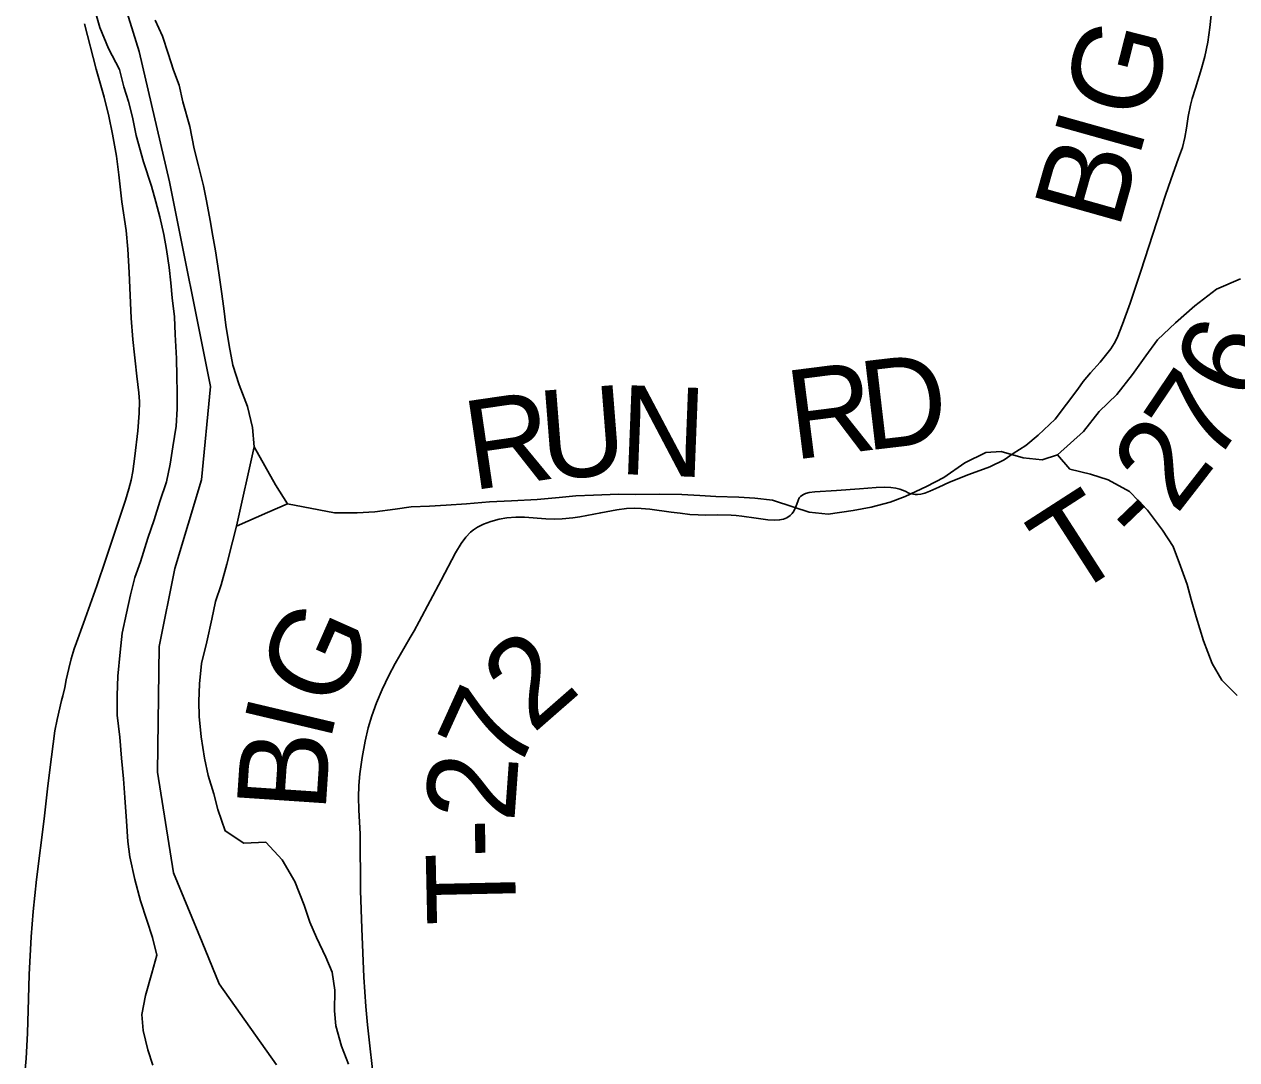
# Model space of a CAD drawing. Extents: x 1451455 to 1749751, y 218250 to 574981.
# Drawn here: x 1553110 to 1557194, y 292724 to 296211 of the extents above; entities that cross this region are included whole.
import ezdxf

# ---------------------------------------------------------------- set-up
doc = ezdxf.new("R2010")
doc.units = 0
for name, color, linetype in [('GM_X_Major_River', 7, 'Continuous'), ('GM_X_Minor_River', 7, 'Continuous'), ('GM_X_State_Route', 7, 'Continuous'), ('GM_X_Township', 7, 'Continuous'), ('GM_X_Township_Road', 7, 'Continuous'), ('GM_X_Township_Road_Text', 7, 'Continuous')]:
    doc.layers.add(name, color=color, linetype=linetype)

msp = doc.modelspace()

# ---------------------------------------------------------------- linework, layer by layer
at = {"layer": 'GM_X_Major_River'}
msp.add_line((1553884.4, 294787.7), (1553824.5, 294520.5), dxfattribs=at)
for points in [[(1553344.3, 296270.7), (1553365.2, 296200.3), (1553394, 296129.9), (1553430.9, 296059.3), (1553446, 296001), (1553461.1, 295950.8), (1553474.3, 295898.5), (1553487.3, 295836.3), (1553511.9, 295747.9), (1553538.6, 295665.5), (1553553.8, 295613.2), (1553567, 295563), (1553580, 295502.8), (1553589.2, 295452.6), (1553598.3, 295392.4), (1553603.5, 295340.3), (1553608.7, 295290.2), (1553615.7, 295226.1), (1553618.8, 295166), (1553623.5, 295085.9), (1553624.6, 295025.8), (1553625.7, 294969.8), (1553624.9, 294915.8), (1553622, 294857.8), (1553611, 294787.9), (1553602.1, 294730), (1553589.2, 294670.2), (1553566.3, 294604.5), (1553547.4, 294542.8), (1553526.5, 294481.1), (1553501.3, 294401.4), (1553482.5, 294347.7), (1553467.7, 294289.9), (1553454.8, 294228), (1553439.7, 294160.2), (1553432.8, 294096.3), (1553425.6, 294016.4), (1553422.6, 293950.4), (1553423.6, 293884.3), (1553432.4, 293810.1), (1553437.3, 293740), (1553444.2, 293669.9), (1553449.3, 293607.8), (1553454, 293527.6), (1553459, 293459.5), (1553466.2, 293407.4), (1553483, 293331.1), (1553501.8, 293258.7), (1553522.8, 293194.4), (1553541.9, 293136), (1553556.9, 293075.8), (1553540, 293016), (1553518.9, 292940.3), (1553506, 292876.4), (1553511.1, 292822.3), (1553526.1, 292758), (1553543.3, 292705.7)], [(1553884.4, 294787.7), (1553879.4, 294853.8), (1553862.5, 294924.1), (1553833.7, 294996.6), (1553812.8, 295063), (1553799.8, 295129.2), (1553788.9, 295197.4), (1553781.8, 295253.5), (1553774.7, 295311.7), (1553765.6, 295373.8), (1553754.8, 295448), (1553745.6, 295498.2), (1553736.4, 295550.4), (1553723.5, 295616.6), (1553714.3, 295666.8), (1553697.3, 295735), (1553682.2, 295791.3), (1553667.4, 295867.5), (1553644.7, 295949.9), (1553631.6, 296006.2), (1553612.4, 296056.5), (1553595.4, 296112.8), (1553576.3, 296171.1), (1553551.2, 296225.5)], [(1553824.5, 294520.5), (1553928.9, 294566.9), (1553997.2, 294595.9), (1553956.3, 294660.6), (1553884.4, 294787.7)], [(1554201.9, 292709.6), (1554178.9, 292770), (1554160, 292838.3), (1554154.8, 292888.4), (1554155.8, 292958.5), (1554146.8, 293018.7), (1554125.6, 293069), (1554094.7, 293135.5), (1554071.5, 293187.9), (1554052.4, 293244.3), (1554021.7, 293324.8), (1553978.9, 293397.5), (1553923.9, 293456.4), (1553850.1, 293453.5), (1553786.8, 293494.5), (1553762, 293566.9), (1553748.8, 293619.2), (1553729.8, 293681.5), (1553716.7, 293739.7), (1553705.8, 293811.9), (1553698.9, 293880.1), (1553697.7, 293930.1), (1553700.6, 293990.1), (1553707.6, 294058.1), (1553724.7, 294131.8), (1553741.8, 294207.6), (1553754.7, 294267.5), (1553773.5, 294323.2), (1553792.6, 294392.9), (1553811.7, 294468.7), (1553824.5, 294520.5)]]:
    msp.add_lwpolyline(points, dxfattribs=at)
at = {"layer": 'GM_X_Minor_River'}
for points in [[(1553997.2, 294595.9), (1554155.1, 294565.6), (1554231, 294566.4), (1554291, 294569.5), (1554359.1, 294578.4), (1554413.2, 294585.6), (1554475.2, 294588.6), (1554531.2, 294591.7), (1554599.3, 294596.6), (1554677.3, 294603.4), (1554751.3, 294606.3), (1554837.3, 294610.9), (1554911.4, 294617.8), (1554967.4, 294622.9), (1555027.4, 294625.9), (1555111.4, 294628.6), (1555167.3, 294627.7), (1555249.3, 294628.4), (1555325.2, 294627.2), (1555385.1, 294624.3), (1555439, 294621.4), (1555516.9, 294618.2), (1555570.8, 294615.4), (1555630.7, 294608.4), (1555702.2, 294585.3), (1555753.9, 294568.4), (1555817.8, 294561.4), (1555901.9, 294574.1), (1555962.1, 294585.2), (1556026.3, 294602.2), (1556076.6, 294621.4), (1556149.1, 294654.3), (1556207.5, 294685.4), (1556278.3, 294734.3), (1556348.8, 294769.2), (1556400.8, 294772.4), (1556474.4, 294751.2), (1556538.3, 294744.2), (1556590.5, 294761.4), (1556677.8, 294840.1), (1556730.8, 294907.3), (1556789.7, 294964.5), (1556842.8, 295031.7), (1556887.8, 295095), (1556926.7, 295148.5), (1556987.6, 295205.6), (1557052.5, 295262.6), (1557125.4, 295319.5), (1557205.9, 295354.2)], [(1556590.5, 294761.4), (1556631.7, 294712.7), (1556701.3, 294695.6), (1556761, 294676.7), (1556832.3, 294637.5), (1556893.2, 294574.5), (1556944, 294507.6), (1556979.1, 294453), (1557004, 294386.6), (1557026.9, 294324.1), (1557040.1, 294273.9), (1557057.1, 294215.6), (1557081.7, 294135.1), (1557110.4, 294058.6), (1557143.5, 294002), (1557194.6, 293951.2)]]:
    msp.add_lwpolyline(points, dxfattribs=at)
at = {"layer": 'GM_X_State_Route'}
msp.add_lwpolyline([(1553110.2, 292653.3), (1553116.4, 292728.6), (1553120.9, 292813.9), (1553124.4, 292928.7), (1553126.6, 293010.7), (1553133.1, 293138.3), (1553140, 293223.1), (1553151.8, 293330.6), (1553177.1, 293535.7), (1553189.5, 293646.6), (1553201.6, 293744.1), (1553213.6, 293831.6), (1553220.5, 293870.1), (1553236, 293933.6), (1553239.9, 293949.4), (1553247.1, 293978), (1553251.8, 294003.8), (1553260.3, 294042.1), (1553268.6, 294073.7), (1553278.5, 294108), (1553286, 294129.5), (1553309.2, 294194.1), (1553354.3, 294320.4), (1553385.2, 294409.8), (1553451.4, 294609), (1553462.6, 294646.9), (1553469.9, 294675.7), (1553475.7, 294704.8), (1553483.1, 294757), (1553492.3, 294841.9), (1553497.1, 294901), (1553498.1, 294940.7), (1553496.3, 294970.4), (1553489.7, 295026), (1553483.5, 295078), (1553481.1, 295097.5), (1553476, 295149.6), (1553470.4, 295221.4), (1553463.4, 295375.4), (1553458.8, 295454.2), (1553453, 295516.4), (1553439.3, 295613.8), (1553428.5, 295704.6), (1553420.4, 295766.5), (1553407.5, 295841), (1553394.6, 295902.1), (1553378.8, 295965.9), (1553352.1, 296060.5), (1553313, 296212.8)], dxfattribs=at)
at = {"layer": 'GM_X_Township'}
msp.add_lwpolyline([(1553394.7, 296450.1), (1553496.8, 296119.5), (1553598.9, 295680.7), (1553737, 294991.4), (1553706.9, 294676.8), (1553616.8, 294378.2), (1553564.7, 294115.7), (1553558.7, 293692.8), (1553612.8, 293354.1), (1553709.1, 293120), (1553766.9, 292979.3), (1553959.2, 292706.6)], dxfattribs=at)
msp.add_lwpolyline([(1553394.7, 296450.1), (1553496.8, 296119.5), (1553598.9, 295680.7), (1553737, 294991.4), (1553706.9, 294676.8), (1553616.8, 294378.2), (1553564.7, 294115.7), (1553558.7, 293692.8), (1553612.8, 293354.1), (1553709.1, 293120), (1553766.9, 292979.3), (1553959.2, 292706.6)], dxfattribs=at)
at = {"layer": 'GM_X_Township_Road'}
for points in [[(1556361.9, 294720.8), (1556410.3, 294744.7), (1556441.1, 294765.6), (1556483.5, 294792.5), (1556525.2, 294827.2), (1556582.2, 294881.2), (1556658.5, 294982.2), (1556677, 295008.4), (1556701.7, 295037.7), (1556734.1, 295073.2), (1556769.7, 295118.2), (1556781, 295135.7), (1556790.9, 295155.7), (1556809.3, 295201.1), (1556834.4, 295271.9), (1556871, 295379.6), (1556924.8, 295546.2), (1556953.4, 295635.4), (1556971.4, 295687.2), (1556998, 295759.9), (1557010.6, 295795.9), (1557018.9, 295829.8), (1557024.8, 295861.9), (1557030.5, 295900.8), (1557038.4, 295939.3), (1557044.1, 295961.5), (1557054.8, 295996), (1557075.2, 296061.8), (1557086, 296103.1), (1557096.1, 296151.2), (1557103.4, 296199.9), (1557107.6, 296242.4)], [(1554290, 292630.1), (1554265.9, 292841.8), (1554260.2, 292903.7), (1554254.3, 293001.9), (1554247.1, 293165.8), (1554242.9, 293293.7), (1554242, 293483.9), (1554237.4, 293565.7), (1554236.1, 293608.3), (1554237.2, 293647.6), (1554240.7, 293686.8), (1554248.4, 293742.1), (1554258.6, 293796.9), (1554269, 293841.6), (1554280.9, 293882.5), (1554296.5, 293925.7), (1554315.6, 293971.1), (1554338.2, 294018.5), (1554359.6, 294059), (1554410.4, 294145.9), (1554423, 294168.8), (1554440.5, 294200.2), (1554514, 294339), (1554563.1, 294431.7), (1554581.7, 294462.7), (1554597.2, 294483.8), (1554612.7, 294500.6), (1554622.8, 294508.9), (1554636.3, 294518.1), (1554656.8, 294528.3), (1554681.5, 294537.2), (1554710.1, 294544.7), (1554736, 294549.1), (1554765.4, 294551.6), (1554794.9, 294551.4), (1554866.7, 294545.9), (1554896.1, 294544.9), (1554922.3, 294545.7), (1554958.1, 294549), (1554980.8, 294552.3), (1555051.5, 294566), (1555106.3, 294576.2), (1555138.8, 294580.1), (1555165, 294581.1), (1555187.9, 294580.6), (1555217.3, 294578.2), (1555288.7, 294568), (1555318.7, 294564.6), (1555351.4, 294560.7), (1555380, 294559.4), (1555402.9, 294558.4), (1555445.4, 294558.9), (1555491.1, 294557.8), (1555507.4, 294556.7), (1555527, 294554.8), (1555575.6, 294547.4), (1555614.6, 294542.2), (1555637.6, 294540.9), (1555654, 294541.9), (1555666.8, 294544.6), (1555678.9, 294549.3), (1555689.7, 294556.5), (1555696.4, 294563.5), (1555701.9, 294571.5), (1555709.1, 294586.2), (1555716.6, 294607.7), (1555720.4, 294616.1), (1555724.4, 294620.7), (1555732.3, 294626.4), (1555741, 294630.8), (1555753.6, 294634.5), (1555773.1, 294636.8), (1555846.2, 294640.8), (1555923.7, 294647.2), (1555979.3, 294651.3), (1556008.3, 294652.7), (1556029, 294651.3), (1556046.1, 294648.7), (1556058.5, 294645.6), (1556076.5, 294639), (1556089.3, 294632.4), (1556099.8, 294629.4), (1556110.4, 294627.7), (1556118.8, 294627.6), (1556129.9, 294629), (1556143, 294632.4), (1556159.7, 294638.6), (1556190.9, 294652.7), (1556226.3, 294669.6), (1556291.8, 294695), (1556361.9, 294720.8)]]:
    msp.add_lwpolyline(points, dxfattribs=at)

# ---------------------------------------------------------------- texts
at = {"layer": 'GM_X_Township_Road_Text'}
for s, rotation, p in [('G', 75.7281, (1556897.7, 295879)), ('I', 74.3487, (1556862.4, 295752.7)), ('B', 74.2511, (1556795.4, 295515)), ('6', 67.2865, (1557250.2, 294929.7)), ('D', 6.6852, (1555944.8, 294775.2)), ('R', 7.2456, (1555701.1, 294744.2)), ('7', 56.0682, (1557116.7, 294720.1)), ('R', 8.2993, (1554618.5, 294641.3)), ('U', 4.5218, (1554857.1, 294676.3)), ('N', 357.7373, (1555110.9, 294697)), ('2', 52.1485, (1556990.2, 294556)), ('T', 32.7784, (1556631.6, 294274.8)), ('-', 43.9281, (1556870.1, 294435.7)), ('G', 66.0995, (1554162.7, 293893.8)), ('2', 41.1443, (1554822.9, 293819.7)), ('7', 65.5614, (1554766.5, 293678.4)), ('I', 76.669, (1554138.9, 293787.7)), ('B', 86.1527, (1554124.4, 293554.8)), ('2', 85.914, (1554760.2, 293521.2)), ('-', 91.0382, (1554762.7, 293405.1)), ('T', 91.2451, (1554767.5, 293181.1))]:
    msp.add_text(s, height=300, rotation=rotation, dxfattribs=at).set_placement(p)

doc.saveas('drawing.dxf')
